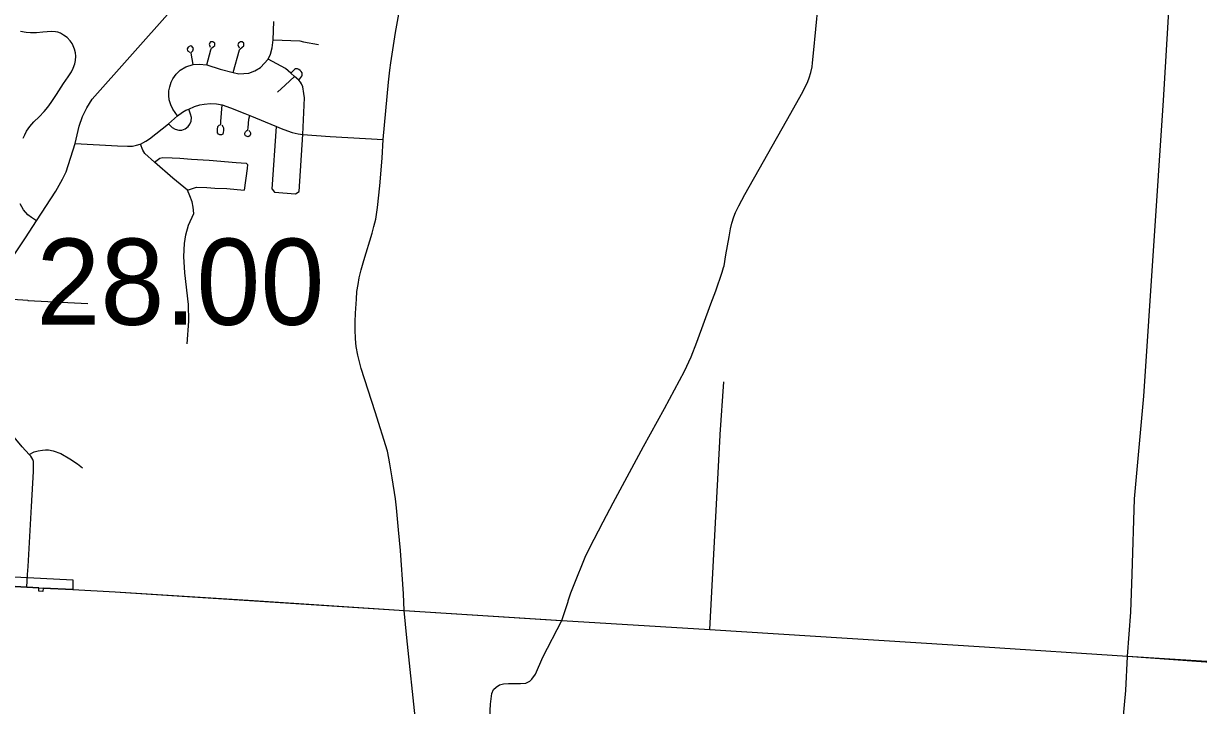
# Model space of a CAD drawing. Extents: x 1729596 to 1934326, y 644115 to 911751.
# Drawn here: x 1876781 to 1891797, y 746694 to 755402 of the extents above; entities that cross this region are included whole.
import ezdxf

# ---------------------------------------------------------------- set-up
doc = ezdxf.new("R2010")
doc.units = 0
for name, color, linetype in [('Default', 7, 'Continuous'), ('GM_X_City_Street', 7, 'Continuous'), ('GM_X_Corporation', 7, 'Continuous'), ('GM_X_County_Road', 7, 'Continuous'), ('GM_X_Township', 7, 'Continuous'), ('GM_X_Township_Road', 7, 'Continuous'), ('GM_X_US_Route', 7, 'Continuous')]:
    doc.layers.add(name, color=color, linetype=linetype)

msp = doc.modelspace()

# ---------------------------------------------------------------- linework, layer by layer
at = {"layer": 'GM_X_City_Street'}
for points in [[(1881635, 748119), (1881635, 748122), (1881597, 748673), (1881573, 748939), (1881547, 749219), (1881533, 749332), (1881494, 749602), (1881463, 749781), (1881451, 749854), (1881432, 749940), (1881273, 750442), (1881097, 750999), (1881055, 751166), (1881034, 751278), (1881024, 751378), (1881019, 751494), (1881020, 751594), (1881025, 751703), (1881035, 751881), (1881042, 751981), (1881056, 752071), (1881069, 752154), (1881097, 752257), (1881131, 752378), (1881235, 752726), (1881257, 752809), (1881282, 752905), (1881305, 753052), (1881336, 753330), (1881363, 753683), (1881379, 753922), (1881444, 754654), (1881461, 754806), (1881476, 754898), (1881535, 755289), (1881632, 755826)], [(1885727, 752287), (1885733, 752309), (1885757, 752447), (1885797, 752679), (1885817, 752780), (1885835, 752852), (1885860, 752933), (1885879, 752989), (1885922, 753073), (1886001, 753218), (1886532, 754159), (1886742, 754531), (1886804, 754660), (1886822, 754710), (1886842, 754776), (1886858, 754851), (1886863, 754901), (1886878, 755025), (1886935, 755638)], [(1876777, 753936), (1876797, 753980), (1876821, 754028), (1876862, 754088), (1876911, 754148), (1876979, 754211), (1877046, 754279), (1877090, 754333), (1877135, 754392), (1877201, 754494), (1877293, 754635), (1877350, 754720), (1877394, 754787), (1877417, 754832), (1877437, 754886), (1877447, 754931), (1877449, 754985), (1877444, 755027), (1877432, 755075), (1877416, 755119), (1877402, 755147), (1877379, 755182), (1877340, 755222), (1877294, 755255), (1877253, 755278), (1877218, 755290), (1877190, 755295), (1877140, 755299), (1877083, 755297), (1877028, 755291), (1876947, 755282), (1876872, 755283), (1876816, 755289), (1876742, 755301)], [(1878750, 754223), (1878691, 754309), (1878663, 754364), (1878643, 754429), (1878637, 754481), (1878640, 754544), (1878649, 754594), (1878668, 754652), (1878690, 754695), (1878730, 754754), (1878784, 754805), (1878854, 754848), (1878948, 754879), (1879027, 754885), (1879125, 754875), (1879296, 754819), (1879462, 754776), (1879534, 754761), (1879595, 754764), (1879661, 754770), (1879736, 754799), (1879811, 754842), (1879907, 754946), (1879939, 755012), (1879959, 755093), (1879971, 755193), (1879982, 755427)], [(1879176, 755065), (1879182, 755088), (1879228, 755123), (1879228, 755152), (1879199, 755170), (1879170, 755167), (1879155, 755139), (1879168, 755101)], [(1879543, 755066), (1879545, 755074), (1879575, 755098), (1879596, 755117), (1879595, 755150), (1879577, 755168), (1879553, 755170), (1879529, 755150), (1879521, 755128), (1879537, 755093)], [(1879971, 755193), (1880311, 755179), (1880358, 755170)], [(1880358, 755170), (1880549, 755136)], [(1878924, 755023), (1878922, 755030), (1878945, 755054), (1878955, 755081), (1878934, 755111), (1878913, 755116), (1878887, 755102), (1878874, 755080), (1878877, 755054), (1878905, 755035)], [(1878948, 754879), (1878924, 755023)], [(1879125, 754875), (1879176, 755065)], [(1879462, 754776), (1879543, 755066)], [(1880349, 753984), (1880373, 754454), (1880365, 754510), (1880351, 754592), (1880334, 754632), (1880319, 754654), (1880300, 754679), (1880243, 754725), (1880198, 754766), (1880129, 754827), (1879907, 754946)], [(1880123, 754615), (1880243, 754725)], [(1880300, 754679), (1880339, 754728), (1880342, 754738), (1880343, 754748), (1880343, 754758), (1880340, 754774), (1880331, 754789), (1880317, 754803), (1880299, 754816), (1880283, 754823), (1880270, 754824), (1880258, 754823), (1880245, 754814), (1880198, 754766)], [(1880027, 754527), (1880123, 754615)], [(1878270, 753861), (1878274, 753862), (1878345, 753899), (1878392, 753931), (1878632, 754123), (1878750, 754223), (1878811, 754269), (1878854, 754294), (1878893, 754310), (1878964, 754344), (1879033, 754363), (1879090, 754372), (1879169, 754379), (1879246, 754376), (1879319, 754362), (1879427, 754327), (1879609, 754254), (1879673, 754226), (1880013, 754085), (1880074, 754060), (1880154, 754030), (1880215, 754010), (1880293, 753994), (1880349, 753984), (1880700, 753960), (1881379, 753922)], [(1878632, 754123), (1878682, 754075), (1878718, 754052), (1878766, 754040), (1878803, 754040), (1878846, 754056), (1878884, 754086), (1878907, 754117), (1878922, 754156), (1878926, 754202), (1878917, 754246), (1878893, 754310)], [(1879304, 754151), (1879319, 754362)], [(1879316, 754104), (1879330, 754088), (1879337, 754071), (1879338, 754038), (1879334, 754011), (1879327, 753990), (1879310, 753979), (1879289, 753979), (1879271, 753988), (1879261, 754007), (1879258, 754050), (1879263, 754085), (1879280, 754103), (1879301, 754112), (1879304, 754151)], [(1879651, 754072), (1879659, 754179), (1879673, 754226)], [(1879659, 754035), (1879673, 754024), (1879682, 754006), (1879682, 753990), (1879672, 753969), (1879650, 753957), (1879618, 753968), (1879609, 753983), (1879609, 754000), (1879617, 754020), (1879633, 754036), (1879649, 754044), (1879651, 754072)], [(1879959, 753288), (1880013, 754085)], [(1880304, 753257), (1880349, 753984)], [(1877439, 753872), (1877984, 753842), (1878110, 753834), (1878172, 753838), (1878224, 753849), (1878270, 753861)], [(1878874, 751314), (1878894, 751603), (1878891, 751815), (1878844, 752219), (1878830, 752427), (1878839, 752594), (1878857, 752703), (1878891, 752827), (1878959, 752976), (1878951, 753055), (1878938, 753127), (1878908, 753203), (1878875, 753276), (1878689, 753428), (1878457, 753631), (1878331, 753744), (1878305, 753785), (1878274, 753862)], [(1878457, 753631), (1878525, 753682), (1878563, 753693), (1878681, 753687), (1878780, 753681), (1878928, 753671), (1879154, 753658), (1879499, 753628), (1879625, 753621), (1879643, 753601), (1879641, 753549), (1879600, 753274)], [(1878875, 753276), (1878992, 753311), (1879125, 753310), (1879227, 753300), (1879381, 753294), (1879600, 753274)], [(1879959, 753288), (1879989, 753248), (1880255, 753229), (1880304, 753257)], [(1876946, 752881), (1876882, 752925), (1876838, 752961), (1876781, 753023), (1876737, 753098)], [(1883743, 748032), (1883776, 748134), (1883816, 748240), (1883960, 748588), (1884014, 748703), (1884187, 749038), (1884316, 749280), (1884702, 750001), (1884971, 750488), (1885226, 750963), (1885313, 751146), (1885385, 751335), (1885566, 751821), (1885629, 751988), (1885710, 752229), (1885727, 752287)], [(1876325, 751910), (1876374, 751898), (1876835, 751868)], [(1876835, 751868), (1876838, 751867), (1877603, 751828)], [(1876833, 748366), (1876839, 748468), (1876881, 749234), (1876907, 749681), (1876910, 749771), (1876908, 749809), (1876899, 749835), (1876887, 749858), (1876873, 749877), (1876853, 749901), (1876763, 749998), (1876639, 750147), (1876529, 750311), (1876433, 750504), (1876327, 750846), (1876284, 750941), (1876247, 751000), (1876207, 751057), (1876154, 751118), (1876080, 751194), (1875979, 751303)], [(1876853, 749901), (1876916, 749931), (1876969, 749946), (1877024, 749955), (1877061, 749958), (1877100, 749958), (1877158, 749947), (1877258, 749911), (1877373, 749842), (1877471, 749780), (1877536, 749727)], [(1874256, 748353), (1874500, 748336), (1876824, 748206), (1876881, 748203)], [(1876824, 748206), (1876833, 748366)], [(1877095, 748191), (1877412, 748174), (1877951, 748147), (1878970, 748081)], [(1878970, 748081), (1879720, 748033)]]:
    msp.add_lwpolyline(points, dxfattribs=at)
at = {"layer": 'GM_X_Corporation'}
msp.add_lwpolyline([(1875335, 748406), (1877412, 748297), (1877412, 748174), (1877032, 748194), (1877030, 748148), (1876978, 748152), (1876978, 748198), (1876824, 748206), (1874500, 748336)], dxfattribs=at)
at = {"layer": 'GM_X_County_Road'}
for points in [[(1890890, 747320), (1890890, 747323), (1890931, 747885), (1890949, 748370), (1890978, 749335), (1891096, 750643), (1891349, 754421), (1891423, 755633), (1891501, 756560), (1891551, 757514)], [(1876881, 748203), (1876978, 748198), (1877032, 748194), (1877095, 748191)], [(1881647, 747908), (1881635, 748119)], [(1879720, 748033), (1881647, 747908)], [(1883661, 747781), (1883741, 748024), (1883743, 748032)], [(1881947, 744855), (1881946, 744868), (1881920, 745445), (1881796, 746469), (1881681, 747558), (1881647, 747908)], [(1881647, 747908), (1883654, 747781)], [(1881946, 744868), (1882382, 744860), (1882546, 744866), (1882582, 744885), (1882618, 744930), (1882658, 745023), (1882668, 745123), (1882747, 746710), (1882766, 746849), (1882787, 746899), (1882823, 746930), (1882865, 746956), (1882913, 746971), (1882978, 746976), (1883131, 746973), (1883202, 746978), (1883250, 747005), (1883277, 747032), (1883322, 747094), (1883418, 747310), (1883661, 747781)], [(1883654, 747781), (1883661, 747781), (1885552, 747665), (1889060, 747443), (1890890, 747323)], [(1890773, 745586), (1890829, 746471), (1890868, 746884), (1890890, 747320)], [(1890890, 747323), (1893595, 747153)]]:
    msp.add_lwpolyline(points, dxfattribs=at)
at = {"layer": 'GM_X_Township'}
msp.add_lwpolyline([(1874500, 748336), (1876824, 748206), (1876978, 748198), (1877032, 748194), (1877412, 748174), (1877951, 748147), (1881647, 747908), (1883661, 747781), (1885552, 747665), (1889060, 747444), (1890890, 747323), (1893596, 747130)], dxfattribs=at)
at = {"layer": 'GM_X_Township_Road'}
for points in [[(1885685, 750154), (1885732, 750828)], [(1885552, 747665), (1885684, 750145), (1885685, 750154)]]:
    msp.add_lwpolyline(points, dxfattribs=at)
at = {"layer": 'GM_X_US_Route'}
msp.add_lwpolyline([(1876171, 751557), (1876256, 751744), (1876325, 751910), (1876506, 752212), (1876807, 752667), (1876946, 752881), (1877196, 753260), (1877279, 753413), (1877324, 753507), (1877439, 753872), (1877494, 754090), (1877534, 754213), (1877567, 754283), (1877589, 754326), (1877657, 754437), (1878655, 755556), (1879084, 756067), (1879427, 756451), (1879564, 756594), (1879778, 756816), (1880124, 757173), (1880423, 757471), (1880681, 757732), (1880757, 757805)], dxfattribs=at)

# ---------------------------------------------------------------- texts
at = {"layer": 'Default'}
msp.add_text('28.00', height=1100, dxfattribs=at).set_placement((1876945, 751555))

doc.saveas('drawing.dxf')
